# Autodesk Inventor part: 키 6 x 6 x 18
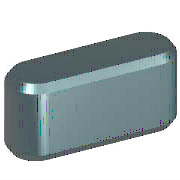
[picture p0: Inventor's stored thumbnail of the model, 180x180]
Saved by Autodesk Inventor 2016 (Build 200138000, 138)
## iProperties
IsCustomPart: 1
Created: 2012-02
Part Number: 키 6 x 6 x 18
Material: 강철, 연강
Description: 키 및 해당 키홈
Document SubType Name: Modeling
Standard: KS B 1311
Designer: mduedu
Standards Organization: KS
Language: ko-KR
Size Designation: 6 x 6 x 18
Categories: <MemberInstance><Categories><Category DisplayName="샤프트 부품" InternalName="7f7aeb1f-a693-4053-b835-cee3144e0d98" Mnemonic="SHFT"><Category DisplayName="키" Interna
Density: 1 g/cm^3
Appearance: 노란색
Author: mduedu
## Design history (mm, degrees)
workplane "Work Plane1"
workplane "Work Plane2"
sketch "스케치1"
  geometry: L1 (3, 3)-(15, 3); L2 (15, -3)-(3, -3); L3 (0, 9.4)-(0, -7.4) reference; L4 (-5, 0)-(30, 0) reference; L5 (18, 0)-(18, 7); A1 r 3 centre (3, 0) between (3, 3) and (3, -3); A2 r 3 centre (15, 0) between (15, -3) and (15, 3)
  constraints: 6 end point, 5 point on circle, 4 tangent, 3 point on line, 2 centre point, 1 horizontal, 1 parallel, 1 perpendicular
  dimensions: "d0" = 3 radius of A1 (= 0.5 x PB); "d13" = 3 radius of A2 (= 0.5 x PB); "d14" = 18 distance between parallel lines of L5 L3 (= NLG)
extrude "본체1" new body sketch "스케치1" taper "d3" = 0 deg; stored distance "d4" = 10
workplane "Work Plane3"
body "Solid1"
chamfer "모따기1" distance "d8" = 0.4 (= PHH); stored, may be unused: second distance "d9" = 0.4 (= PHH), angle "d15" = 45 deg
other parameters: "d1" = -3.5 (= -PNT), "d2" = 2.5 (= PH - PNT), "NLG" = 18 [user parameter; used in 3 equation terms], "PB" = 6 [user parameter; used in 2 equation terms], "PNT" = 3.5 [user parameter; used in 2 equation terms], "PH" = 6 [user parameter; used in 1 equation term], "PHH" = 0.4 [user parameter; used in 2 equation terms], "d10" = 0, "d16" = 0, "d17" = 0, "d18" = 0, "WDMIN" = 17 [user parameter], "PLB2" = 18 (= NLG) [user parameter], "WDMAX" = 22 [user parameter], "PLB1" = 18 (= NLG) [user parameter], "RR" = 0.16 [user parameter], "PUEB" = 2.8 [user parameter]
